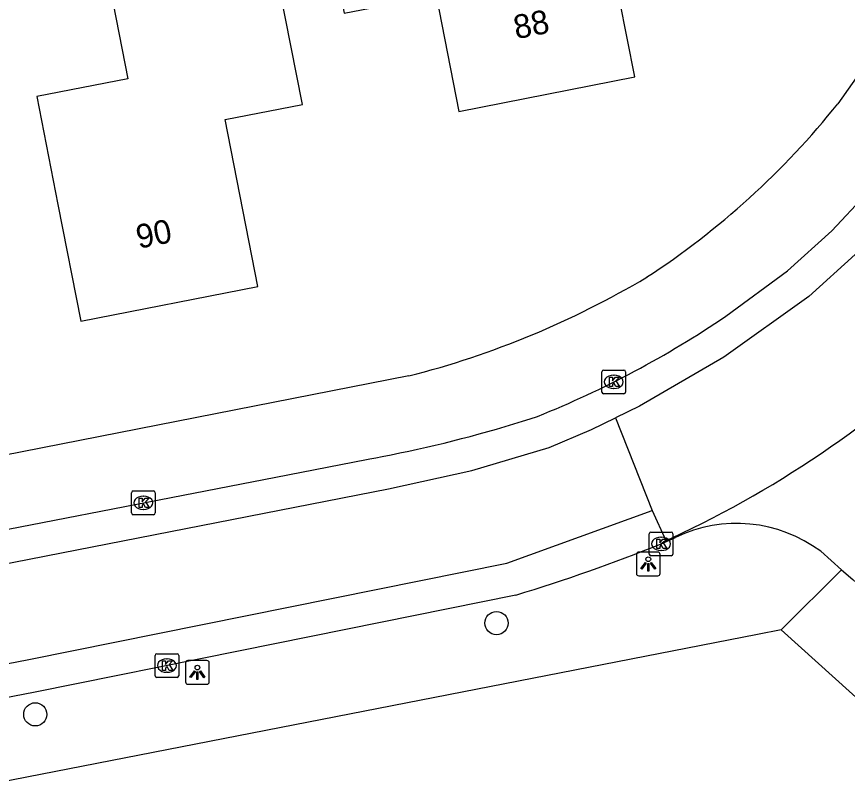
# Model space of a CAD drawing. Extents: x 157663 to 158496, y 379212 to 380934.
# Drawn here: x 158281.71 to 158316.7, y 380315.62 to 380348.23 of the extents above; entities that cross this region are included whole.
import ezdxf

# ---------------------------------------------------------------- set-up
doc = ezdxf.new("R2010")
doc.units = 0
for name, color, linetype in [('IMGEO_Boom', 7, 'Continuous'), ('IMGEO_Kolk', 7, 'Continuous'), ('IMGEO_Lichtpunt', 7, 'Continuous'), ('IMGEO_Pand', 7, 'Continuous'), ('IMGEO_Pand_nummerreeks', 7, 'Continuous'), ('IMGEO_Rijbaan_lokaal_gesloten', 7, 'Continuous'), ('IMGEO_Rijbaan_lokaal_open', 7, 'Continuous'), ('IMGEO_Voetpad_open', 7, 'Continuous')]:
    doc.layers.add(name, color=color, linetype=linetype)

msp = doc.modelspace()

# ---------------------------------------------------------------- linework, layer by layer
at = {"layer": 'IMGEO_Boom'}
for centre in [(158301.923, 380322.671), (158282.496, 380318.825)]:
    msp.add_circle(centre, 0.489, dxfattribs=at)
at = {"layer": 'IMGEO_Kolk'}
for p, q in [((158306.361, 380332.409), (158306.361, 380333.261)), ((158306.436, 380333.335), (158307.288, 380333.335)), ((158306.849, 380333.115), (158306.874, 380333.115)), ((158307.362, 380333.261), (158307.362, 380332.409)), ((158307.288, 380332.335), (158306.436, 380332.335)), ((158306.872, 380332.555), (158306.847, 380332.555)), ((158286.548, 380327.313), (158286.548, 380328.165)), ((158286.623, 380328.239), (158287.475, 380328.239)), ((158287.549, 380328.165), (158287.549, 380327.313)), ((158287.036, 380328.019), (158287.061, 380328.019)), ((158287.059, 380327.459), (158287.034, 380327.459)), ((158287.475, 380327.239), (158286.623, 380327.239)), ((158308.355, 380325.582), (158308.355, 380326.434)), ((158308.43, 380326.508), (158309.282, 380326.508)), ((158309.356, 380326.434), (158309.356, 380325.582)), ((158308.843, 380326.288), (158308.868, 380326.288)), ((158308.866, 380325.728), (158308.841, 380325.728)), ((158309.282, 380325.508), (158308.43, 380325.508)), ((158287.54, 380320.453), (158287.54, 380321.305)), ((158287.615, 380321.379), (158288.467, 380321.379)), ((158288.028, 380321.159), (158288.053, 380321.159)), ((158288.541, 380321.305), (158288.541, 380320.453)), ((158288.051, 380320.599), (158288.026, 380320.599)), ((158288.467, 380320.379), (158287.615, 380320.379))]:
    msp.add_line(p, q, dxfattribs=at)
for points in [[(158306.361, 380332.409), (158306.361, 380333.261)], [(158306.436, 380333.335), (158307.288, 380333.335)], [(158306.682, 380333.035), (158306.805, 380333.035), (158306.805, 380332.884), (158306.935, 380333.035), (158307.099, 380333.035), (158306.953, 380332.884), (158307.106, 380332.635), (158306.954, 380332.635), (158306.869, 380332.799), (158306.805, 380332.732), (158306.805, 380332.635), (158306.682, 380332.635), (158306.682, 380333.035)], [(158307.362, 380333.261), (158307.362, 380332.409)], [(158307.288, 380332.335), (158306.436, 380332.335)], [(158286.548, 380327.313), (158286.548, 380328.165)], [(158286.623, 380328.239), (158287.475, 380328.239)], [(158287.549, 380328.165), (158287.549, 380327.313)], [(158286.869, 380327.939), (158286.992, 380327.939), (158286.992, 380327.788), (158287.122, 380327.939), (158287.286, 380327.939), (158287.14, 380327.788), (158287.293, 380327.539), (158287.141, 380327.539), (158287.056, 380327.703), (158286.992, 380327.636), (158286.992, 380327.539), (158286.869, 380327.539), (158286.869, 380327.939)], [(158287.475, 380327.239), (158286.623, 380327.239)], [(158308.355, 380325.582), (158308.355, 380326.434)], [(158308.43, 380326.508), (158309.282, 380326.508)], [(158309.356, 380326.434), (158309.356, 380325.582)], [(158308.676, 380326.208), (158308.799, 380326.208), (158308.799, 380326.057), (158308.929, 380326.208), (158309.093, 380326.208), (158308.947, 380326.057), (158309.1, 380325.808), (158308.948, 380325.808), (158308.863, 380325.972), (158308.799, 380325.905), (158308.799, 380325.808), (158308.676, 380325.808), (158308.676, 380326.208)], [(158309.282, 380325.508), (158308.43, 380325.508)], [(158287.54, 380320.453), (158287.54, 380321.305)], [(158287.615, 380321.379), (158288.467, 380321.379)], [(158288.541, 380321.305), (158288.541, 380320.453)], [(158287.861, 380321.079), (158287.984, 380321.079), (158287.984, 380320.928), (158288.114, 380321.079), (158288.278, 380321.079), (158288.132, 380320.928), (158288.285, 380320.679), (158288.133, 380320.679), (158288.048, 380320.843), (158287.984, 380320.776), (158287.984, 380320.679), (158287.861, 380320.679), (158287.861, 380321.079)], [(158288.467, 380320.379), (158287.615, 380320.379)]]:
    msp.add_lwpolyline(points, dxfattribs=at)
for centre, start, end in [((158306.438, 380333.259), 91.552, 178.448), ((158306.438, 380333.259), 91.552, 178.448), ((158307.286, 380333.259), 1.552, 88.448), ((158307.286, 380333.259), 1.552, 88.448), ((158306.438, 380332.411), 181.552, 268.448), ((158306.438, 380332.411), 181.552, 268.448), ((158307.286, 380332.411), 271.552, 358.448), ((158307.286, 380332.411), 271.552, 358.448), ((158286.625, 380328.163), 91.552, 178.448), ((158286.625, 380328.163), 91.552, 178.448), ((158287.473, 380328.163), 1.552, 88.448), ((158287.473, 380328.163), 1.552, 88.448), ((158286.625, 380327.315), 181.552, 268.448), ((158286.625, 380327.315), 181.552, 268.448), ((158287.473, 380327.315), 271.552, 358.448), ((158287.473, 380327.315), 271.552, 358.448), ((158308.432, 380326.432), 91.552, 178.448), ((158308.432, 380326.432), 91.552, 178.448), ((158309.28, 380326.432), 1.552, 88.448), ((158309.28, 380326.432), 1.552, 88.448), ((158308.432, 380325.584), 181.552, 268.448), ((158308.432, 380325.584), 181.552, 268.448), ((158309.28, 380325.584), 271.552, 358.448), ((158309.28, 380325.584), 271.552, 358.448), ((158287.617, 380321.303), 91.552, 178.448), ((158287.617, 380321.303), 91.552, 178.448), ((158288.465, 380321.303), 1.552, 88.448), ((158288.465, 380321.303), 1.552, 88.448), ((158287.617, 380320.455), 181.552, 268.448), ((158287.617, 380320.455), 181.552, 268.448), ((158288.465, 380320.455), 271.552, 358.448), ((158288.465, 380320.455), 271.552, 358.448)]:
    msp.add_arc(centre, 0.0765, start, end, dxfattribs=at)
for centre, major_axis, ratio, start_param, end_param in [((158306.848, 380332.835), (-0.387, 0.002), 0.722429, 4.712389, 7.853982), ((158306.873, 380332.835), (-0.39, 0.002), 0.717154, 1.570796, 4.712389), ((158287.035, 380327.739), (-0.387, 0.002), 0.722429, 4.712389, 7.853982), ((158287.06, 380327.739), (-0.39, 0.002), 0.717154, 1.570796, 4.712389), ((158308.842, 380326.008), (-0.387, 0.002), 0.722429, 4.712389, 7.853982), ((158308.867, 380326.008), (-0.39, 0.002), 0.717154, 1.570796, 4.712389), ((158288.027, 380320.879), (-0.387, 0.002), 0.722429, 4.712389, 7.853982), ((158288.052, 380320.879), (-0.39, 0.002), 0.717154, 1.570796, 4.712389)]:
    msp.add_ellipse(centre, major_axis=major_axis, ratio=ratio, start_param=start_param, end_param=end_param, dxfattribs=at)
at = {"layer": 'IMGEO_Lichtpunt'}
for p, q in [((158308.721, 380325.661), (158307.913, 380325.661)), ((158308.721, 380325.661), (158307.913, 380325.661)), ((158307.819, 380325.566), (158307.819, 380324.759)), ((158307.819, 380325.566), (158307.819, 380324.759)), ((158308.815, 380324.759), (158308.815, 380325.566)), ((158308.815, 380324.759), (158308.815, 380325.566)), ((158307.913, 380324.665), (158308.721, 380324.665)), ((158307.913, 380324.665), (158308.721, 380324.665)), ((158288.825, 380320.998), (158288.825, 380320.191)), ((158288.825, 380320.998), (158288.825, 380320.191)), ((158289.727, 380321.093), (158288.919, 380321.093)), ((158289.727, 380321.093), (158288.919, 380321.093)), ((158289.821, 380320.191), (158289.821, 380320.998)), ((158289.821, 380320.191), (158289.821, 380320.998)), ((158288.919, 380320.097), (158289.727, 380320.097)), ((158288.919, 380320.097), (158289.727, 380320.097))]:
    msp.add_line(p, q, dxfattribs=at)
for points in [[(158308.193, 380325.23), (158308.232, 380325.202), (158308.044, 380324.94), (158308.006, 380324.967), (158308.193, 380325.23)], [(158308.295, 380325.182), (158308.342, 380325.182), (158308.342, 380324.86), (158308.295, 380324.86), (158308.295, 380325.182)], [(158308.405, 380325.202), (158308.443, 380325.229), (158308.63, 380324.967), (158308.591, 380324.939), (158308.405, 380325.202)], [(158289.199, 380320.662), (158289.238, 380320.634), (158289.05, 380320.372), (158289.012, 380320.399), (158289.199, 380320.662)], [(158289.301, 380320.614), (158289.348, 380320.614), (158289.348, 380320.292), (158289.301, 380320.292), (158289.301, 380320.614)], [(158289.411, 380320.634), (158289.449, 380320.661), (158289.636, 380320.399), (158289.597, 380320.371), (158289.411, 380320.634)]]:
    msp.add_lwpolyline(points, dxfattribs=at)
for centre in [(158308.318, 380325.364), (158289.324, 380320.796)]:
    msp.add_circle(centre, 0.0994, dxfattribs=at)
for centre, start, end in [((158307.913, 380325.566), 90, 180), ((158307.913, 380325.566), 90, 180), ((158308.721, 380325.566), 0, 90), ((158308.721, 380325.566), 0, 90), ((158307.913, 380324.759), 180, 270), ((158307.913, 380324.759), 180, 270), ((158308.721, 380324.759), 270, 0), ((158308.721, 380324.759), 270, 360), ((158288.919, 380320.998), 90, 180), ((158288.919, 380320.998), 90, 180), ((158289.727, 380320.998), 0, 90), ((158289.727, 380320.998), 0, 90), ((158288.919, 380320.191), 180, 270), ((158288.919, 380320.191), 180, 270), ((158289.727, 380320.191), 270, 0), ((158289.727, 380320.191), 270, 360)]:
    msp.add_arc(centre, 0.0946, start, end, dxfattribs=at)
at = {"layer": 'IMGEO_Pand'}
for points in [[(158306.785, 380350.592), (158306.049, 380354.347), (158302.218, 380353.596), (158301.445, 380357.542), (158294.003, 380356.083), (158294.551, 380353.286), (158295.512, 380348.379), (158299.378, 380349.137), (158300.339, 380344.234), (158307.746, 380345.685), (158306.785, 380350.592)], [(158290.06, 380350.961), (158285.518, 380350.071), (158286.392, 380345.612), (158282.558, 380344.86), (158283.45, 380340.306), (158284.412, 380335.399), (158291.876, 380336.862), (158290.498, 380343.891), (158293.75, 380344.528), (158292.789, 380349.435), (158292.4, 380351.42)]]:
    msp.add_lwpolyline(points, dxfattribs=at)
at = {"layer": 'IMGEO_Rijbaan_lokaal_gesloten'}
for points in [[(158357.742, 380399.152), (158349.792, 380387.036), (158321.746, 380343.769), (158319.987, 380341.493), (158318.518, 380339.79), (158317.032, 380338.206), (158315.073, 380336.434), (158311.501, 380333.875), (158307.953, 380331.819), (158306.936, 380331.323)], [(158311.589, 380335.61), (158314.186, 380337.52), (158316.05, 380339.206), (158317.471, 380340.72), (158318.142, 380341.518)], [(158252.411, 380320.956), (158252.667, 380319.58), (158297.379, 380328.323), (158300.886, 380329.108), (158304.148, 380330.07), (158305.918, 380330.827), (158306.936, 380331.323)], [(158303.016, 380331.177), (158303.336, 380331.279), (158303.655, 380331.382)], [(158306.936, 380331.323), (158308.481, 380327.416)], [(158252.411, 380320.956), (158263.179, 380323.088), (158267.707, 380323.97), (158272.297, 380324.864), (158276.425, 380325.668), (158292.631, 380328.824), (158296.448, 380329.568), (158296.582, 380329.594), (158296.844, 380329.642), (158297.106, 380329.691)], [(158208.15, 380306.752), (158234.449, 380311.859), (158253.417, 380315.54), (158282.223, 380321.13), (158302.352, 380325.202), (158308.481, 380327.416)], [(158308.481, 380327.416), (158309.051, 380326.149)], [(158309.051, 380326.149), (158308.856, 380326.008)], [(158309.051, 380326.149), (158309.29, 380326.255)], [(158302.731, 380323.85), (158297.03, 380322.697), (158291.127, 380321.503), (158282.495, 380319.757), (158272.265, 380317.78), (158267.99, 380316.953), (158253.663, 380314.213), (158236.263, 380310.779), (158234.715, 380310.488), (158231.813, 380309.91), (158196.789, 380303.085), (158190.936, 380301.977), (158182.046, 380300.295), (158181.583, 380300.207), (158174.809, 380298.869), (158168.769, 380297.676), (158152.391, 380294.441), (158150.782, 380294.149)]]:
    msp.add_lwpolyline(points, dxfattribs=at)
for centre, radius, start, end in [((158287.714, 380370.853), 42.569, 291.9915, 304.1145), ((158290.92, 380366.091), 43.868, 294.7566, 314.9522), ((158287.143, 380381.81), 53.062, 280.8219, 287.4057), ((158279.983, 380398.187), 77.74, 287.01491, 291.80252)]:
    msp.add_arc(centre, radius, start, end, dxfattribs=at)
at = {"layer": 'IMGEO_Rijbaan_lokaal_open'}
for points in [[(158308.856, 380326.008), (158309.458, 380326.281)], [(158315.578, 380325.699), (158316.461, 380324.918)], [(158316.461, 380324.918), (158316.931, 380324.502), (158319.899, 380321.823), (158358.695, 380287.026)]]:
    msp.add_lwpolyline(points, dxfattribs=at)
msp.add_arc((158312.036, 380320.921), 5.948, 53.45, 115.6853, dxfattribs=at)
at = {"layer": 'IMGEO_Voetpad_open'}
for points in [[(158351.3, 380398.128), (158318.204, 380347.27), (158316.304, 380344.56)], [(158298.234, 380333.084), (158263.218, 380326.206)], [(158316.461, 380324.918), (158313.914, 380322.39)], [(158313.914, 380322.39), (158312.921, 380322.194), (158264.365, 380312.705), (158256.222, 380311.09), (158254.843, 380310.82)], [(158362.946, 380278.347), (158355.536, 380284.979), (158355.63, 380285.086), (158319.878, 380317.192), (158319.785, 380317.098), (158313.914, 380322.39)]]:
    msp.add_lwpolyline(points, dxfattribs=at)
for centre, radius, start, end in [((158289.328, 380366.163), 34.56, 303.1923, 321.3111), ((158288.782, 380369.986), 38.093, 284.3669, 300.7313)]:
    msp.add_arc(centre, radius, start, end, dxfattribs=at)

# ---------------------------------------------------------------- texts
at = {"layer": 'IMGEO_Pand_nummerreeks'}
for s, rotation, p in [('88', 11.0836, (158302.75, 380347.273)), ('90', 11.0925, (158286.85, 380338.444))]:
    msp.add_text(s, height=1, rotation=rotation, dxfattribs=at).set_placement(p)

doc.saveas('drawing.dxf')
